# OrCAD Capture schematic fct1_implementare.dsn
size A
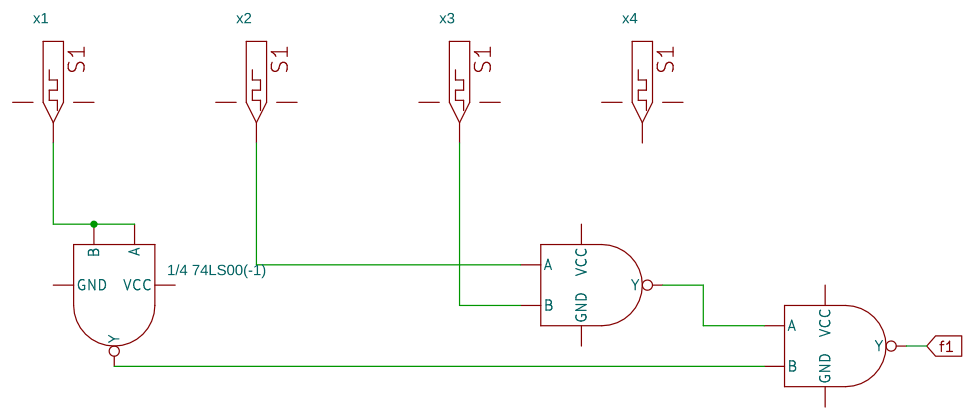
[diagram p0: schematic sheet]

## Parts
U3  74LS00  [DIP.100/14/W.300/L.800]  (sections A,B)
U4  74LS00  [DIP.100/14/W.300/L.800]  (section B)
x1  DigStim1
x2  DigStim1
x3  DigStim1
x4  DigStim1

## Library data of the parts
U3 U4 = 74LS00
x1-x4 = DigStim1

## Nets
GND: U3.7(GND) U4.7(GND) x1.3(GND) x2.3(GND) x3.3(GND) x4.3(GND)
VCC: U3.14(VCC) U4.14(VCC) x1.2(VCC) x2.2(VCC) x3.2(VCC) x4.2(VCC)
f1: U4.6(Y)
N14631: U3.1(A) U3.2(B) x1.OUT
N14720: U3.4(A) x2.OUT
N14727: U3.5(B) x3.OUT
N14814: U3.6(Y) U4.4(A)
N14826: U3.3(Y) U4.5(B)

Not connected (* = marked no-connect by the designer): x4 OUT
